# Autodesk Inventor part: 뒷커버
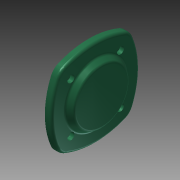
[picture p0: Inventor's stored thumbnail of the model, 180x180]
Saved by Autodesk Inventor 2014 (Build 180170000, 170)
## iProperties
Created: 2015-11
Part Number: 뒷커버
Material: 알루미늄 6061
Document SubType Name: Modeling
Designer: mduedu
Density: 2.71 g/cm^3
Mass: 325.35 g
Surface Area: 247.582 cm^2
Volume: 120.055 cm^3
Appearance: 매끄러움 - 짙은 바다 녹색
Author: mduedu
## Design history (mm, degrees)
sketch "스케치1"
  geometry: L1 (50, 50)-(-50, 50); L2 (-50, 50)-(-50, -50); L3 (-50, -50)-(50, -50); L4 (50, -50)-(50, 50); L5 (0, 50)-(0, -50); L6 (50, 0)-(-50, 0); A1 r 90 centre (-40, 0) between (40.415, -40.415) and (40.415, 40.415); A2 r 90 centre (40, 0) between (-40.415, 40.415) and (-40.415, -40.415); A3 r 90 centre (0, -40) between (40.415, 40.415) and (-40.415, 40.415); A4 r 90 centre (0, 40) between (-40.415, -40.415) and (40.415, -40.415); 2 further points
  constraints: 12 end point, 8 point on circle, 5 midpoint, 4 centre point, 2 horizontal alignment, 2 parallel, 2 perpendicular, 2 symmetric about line, 2 tangent, 2 vertical alignment, 1 equal radius, 1 horizontal, 2 other
  dimensions: "d0" = 100 distance of L3.end L1.start; "d2" = 90 radius of A1
extrude "돌출1" new body sketch "스케치1" distance "d3" = 8; taper "d4" = 0 deg
sketch "스케치2"
  geometry: C1 r 35 at (0, 0); 1 further point
  constraints: 1 centre point, 1 coincident
  dimensions: "d5" = 70 diameter of C1
extrude "돌출2" join sketch "스케치2" distance "d6" = 7; taper "d7" = -30 deg
sketch "스케치3"
  geometry: L1 (0, 0)-(0, 40); L2 (0, 0)-(-28.284, 28.284); A1 r 40 centre (0, 0) between (0, 40) and (-28.284, 28.284); 2 further points
  constraints: 4 end point, 2 coincident, 2 point on circle, 1 centre point, 1 vertical
  dimensions: "d8" = 80 diameter of A1; "d9" = 45 deg angle of L1 L2
hole "구멍1" sketch "스케치3" at (-28.284, 28.284) diameter "d11" = 4.5; stored, may be unused: countersink angle "d15" = 90 deg, drill point angle "d17" = 118 deg; dims "d12" = 6, "d13" = 8, "d14" = 4.4, "d16" = 8
sketch "스케치4"
  geometry: C1 r 35 at (0, 0); 1 further point
  constraints: 1 centre point, 1 coincident
  dimensions: "d21" = 70 diameter of C1
extrude "돌출3" join sketch "스케치4" distance "d23" = 12; taper "d24" = 0 deg
hole "구멍2" diameter "d27" = 30; stored, may be unused: countersink angle "d31" = 90 deg, drill point angle "d33" = 0 deg; dims "d25" = 10, "d26" = 10, "d28" = 6, "d29" = 40, "d30" = 12, "d32" = 15
fillet "모깎기2" dims "d35" = 15
fillet "모깎기3" dims "d36" = 3
fillet "모깎기4" dims "d37" = 3
fillet "모깎기5" dims "d38" = 0.3
chamfer "모따기1" distance "d39" = 1; stored, may be unused: second distance "d40" = 2, angle "d41" = 45 deg
node "솔리드1"
pattern_circular "원형 패턴1" dims angle "d19" = 360 deg
